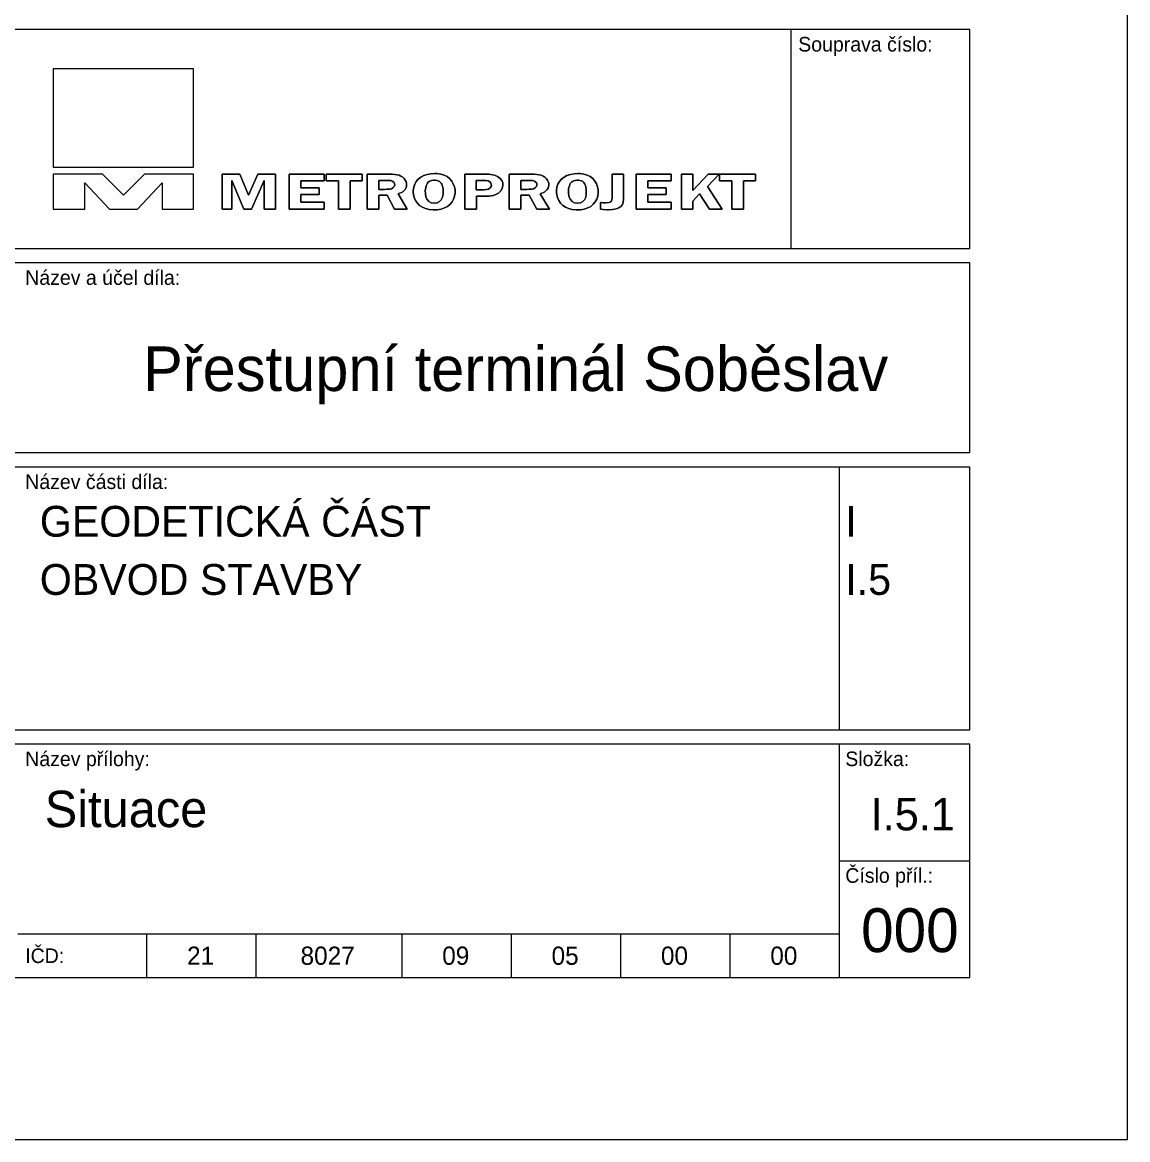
# Model space of a CAD drawing. Extents: x 0.336 to 0.63, y 0 to 0.297.
# Drawn here: x 0.4935 to 0.63, y 0 to 0.1379 of the extents above; entities that cross this region are included whole.
import ezdxf

# ---------------------------------------------------------------- set-up
doc = ezdxf.new("R2010")
doc.units = 0
doc.layers.add('ROZPISKA', color=7, linetype='Continuous')
doc.layers.add('Rozvrzeni', color=7, linetype='Continuous')

msp = doc.modelspace()

# ---------------------------------------------------------------- linework, layer by layer
at = {"layer": 'ROZPISKA'}
for p, q in [((0.51469, 0.13217), (0.49735, 0.13217)), ((0.49735, 0.13217), (0.49735, 0.12003)), ((0.51469, 0.12003), (0.51469, 0.13217)), ((0.49735, 0.12003), (0.51469, 0.12003)), ((0.50342, 0.11916), (0.49735, 0.11916)), ((0.49735, 0.11916), (0.49735, 0.11483)), ((0.50602, 0.11656), (0.50342, 0.11916)), ((0.50862, 0.11916), (0.50602, 0.11656)), ((0.51469, 0.11916), (0.50862, 0.11916)), ((0.51469, 0.11483), (0.51469, 0.11916)), ((0.5182, 0.11483), (0.5182, 0.11918)), ((0.5182, 0.11918), (0.52041, 0.11918)), ((0.52041, 0.11918), (0.52147, 0.11658)), ((0.52147, 0.11658), (0.5226, 0.11918)), ((0.5226, 0.11918), (0.52481, 0.11918)), ((0.52481, 0.11918), (0.52481, 0.11483)), ((0.52647, 0.11483), (0.52647, 0.11918)), ((0.52647, 0.11918), (0.53081, 0.11918)), ((0.53081, 0.11918), (0.53081, 0.11835)), ((0.53107, 0.11832), (0.53107, 0.11918)), ((0.53107, 0.11918), (0.53551, 0.11918)), ((0.53551, 0.11918), (0.53551, 0.11832)), ((0.56932, 0.11483), (0.56932, 0.11918)), ((0.56932, 0.11918), (0.57366, 0.11918)), ((0.57366, 0.11918), (0.57366, 0.11835)), ((0.57492, 0.11483), (0.57492, 0.11918)), ((0.57492, 0.11918), (0.57631, 0.11918)), ((0.57631, 0.11713), (0.57821, 0.11918)), ((0.57631, 0.11918), (0.57631, 0.11713)), ((0.57956, 0.11918), (0.57811, 0.11763)), ((0.57821, 0.11918), (0.57956, 0.11918)), ((0.57963, 0.11832), (0.57963, 0.11918)), ((0.57963, 0.11918), (0.58407, 0.11918)), ((0.58407, 0.11918), (0.58407, 0.11832)), ((0.50125, 0.11483), (0.50125, 0.11808)), ((0.50125, 0.11808), (0.50429, 0.11483)), ((0.50776, 0.11483), (0.51079, 0.11808)), ((0.51079, 0.11808), (0.51079, 0.11483)), ((0.51939, 0.11838), (0.51939, 0.11483)), ((0.52088, 0.11483), (0.51939, 0.11838)), ((0.52338, 0.11838), (0.52185, 0.11483)), ((0.52338, 0.11483), (0.52338, 0.11838)), ((0.52792, 0.11835), (0.52792, 0.11746)), ((0.53081, 0.11835), (0.52792, 0.11835)), ((0.52792, 0.11746), (0.53019, 0.11746)), ((0.53019, 0.11746), (0.53019, 0.11664)), ((0.53258, 0.11832), (0.53107, 0.11832)), ((0.53258, 0.11483), (0.53258, 0.11832)), ((0.53551, 0.11832), (0.53401, 0.11832)), ((0.53401, 0.11832), (0.53401, 0.11483)), ((0.57077, 0.11835), (0.57077, 0.11746)), ((0.57366, 0.11835), (0.57077, 0.11835)), ((0.57077, 0.11746), (0.57304, 0.11746)), ((0.57304, 0.11746), (0.57304, 0.11664)), ((0.57811, 0.11763), (0.57993, 0.11483)), ((0.58113, 0.11832), (0.57963, 0.11832)), ((0.58113, 0.11483), (0.58113, 0.11832)), ((0.58407, 0.11832), (0.58257, 0.11832)), ((0.58257, 0.11832), (0.58257, 0.11483)), ((0.53019, 0.11664), (0.52792, 0.11664)), ((0.52792, 0.11664), (0.52792, 0.11569)), ((0.57304, 0.11664), (0.57077, 0.11664)), ((0.57077, 0.11664), (0.57077, 0.11569)), ((0.57716, 0.11672), (0.57631, 0.11583)), ((0.57836, 0.11483), (0.57716, 0.11672)), ((0.49735, 0.11483), (0.50125, 0.11483)), ((0.50429, 0.11483), (0.50776, 0.11483)), ((0.51079, 0.11483), (0.51469, 0.11483)), ((0.51939, 0.11483), (0.5182, 0.11483)), ((0.52185, 0.11483), (0.52088, 0.11483)), ((0.52481, 0.11483), (0.52338, 0.11483)), ((0.53081, 0.11483), (0.52647, 0.11483)), ((0.52792, 0.11569), (0.53081, 0.11569)), ((0.53081, 0.11569), (0.53081, 0.11483)), ((0.53401, 0.11483), (0.53258, 0.11483)), ((0.57366, 0.11483), (0.56932, 0.11483)), ((0.57077, 0.11569), (0.57366, 0.11569)), ((0.57366, 0.11569), (0.57366, 0.11483)), ((0.57631, 0.11483), (0.57492, 0.11483)), ((0.57631, 0.11583), (0.57631, 0.11483)), ((0.57993, 0.11483), (0.57836, 0.11483)), ((0.58257, 0.11483), (0.58113, 0.11483))]:
    msp.add_line(p, q, dxfattribs=at)
for points in [[(0.4395, 0.11), (0.6105, 0.11), (0.6105, 0.137), (0.4395, 0.137)], [(0.53982, 0.1191), (0.54007, 0.11902), (0.54029, 0.11893), (0.5405, 0.11879), (0.54068, 0.11863), (0.54082, 0.11844), (0.54093, 0.11824), (0.54099, 0.11802), (0.54099, 0.11781), (0.54096, 0.11763), (0.5409, 0.11745), (0.5408, 0.11729), (0.54067, 0.11713), (0.54051, 0.117), (0.54035, 0.1169), (0.54014, 0.11681), (0.54, 0.11677), (0.53995, 0.11675), (0.54107, 0.11483), (0.5395, 0.11483), (0.53857, 0.11655), (0.53755, 0.11655), (0.53755, 0.11483), (0.53612, 0.11483), (0.53612, 0.11918), (0.53879, 0.11918), (0.53919, 0.11917), (0.53953, 0.11914)], [(0.54629, 0.11861), (0.54655, 0.11831), (0.54675, 0.11798), (0.54689, 0.11761), (0.54697, 0.11723), (0.54697, 0.11684), (0.54691, 0.11645), (0.54678, 0.11608), (0.54659, 0.11574), (0.54635, 0.11544), (0.54604, 0.11519), (0.54567, 0.115), (0.54524, 0.11486), (0.54476, 0.11478), (0.54425, 0.11477), (0.54375, 0.11481), (0.54331, 0.11492), (0.54293, 0.11509), (0.54259, 0.11531), (0.54231, 0.1156), (0.54208, 0.11593), (0.54192, 0.11628), (0.54183, 0.11667), (0.54181, 0.11686), (0.54181, 0.11697), (0.54181, 0.11713), (0.54187, 0.11755), (0.54199, 0.11793), (0.54218, 0.11827), (0.54243, 0.11856), (0.54274, 0.11881), (0.54311, 0.119), (0.54352, 0.11914), (0.54398, 0.11922), (0.54445, 0.11925), (0.54471, 0.11924), (0.54519, 0.11917), (0.54561, 0.11905), (0.54598, 0.11886)], [(0.55081, 0.11918), (0.55112, 0.11917), (0.55139, 0.11914), (0.55183, 0.11905), (0.55219, 0.11888), (0.55251, 0.11866), (0.55273, 0.1184), (0.55285, 0.1181), (0.55288, 0.11776), (0.5528, 0.11741), (0.55262, 0.11709), (0.55234, 0.11683), (0.55201, 0.11664), (0.55165, 0.11652), (0.55143, 0.11649), (0.55118, 0.11646), (0.55089, 0.11645), (0.55072, 0.11645), (0.55064, 0.11645), (0.54963, 0.11645), (0.54963, 0.11483), (0.54818, 0.11483), (0.54818, 0.11918), (0.55062, 0.11918)], [(0.55736, 0.1191), (0.55761, 0.11902), (0.55783, 0.11893), (0.55804, 0.11879), (0.55822, 0.11863), (0.55837, 0.11844), (0.55847, 0.11824), (0.55853, 0.11802), (0.55854, 0.11781), (0.55851, 0.11763), (0.55844, 0.11745), (0.55834, 0.11729), (0.55821, 0.11713), (0.55805, 0.117), (0.55789, 0.1169), (0.55768, 0.11681), (0.55755, 0.11677), (0.55749, 0.11675), (0.55861, 0.11483), (0.55704, 0.11483), (0.55611, 0.11655), (0.55509, 0.11655), (0.55509, 0.11483), (0.55366, 0.11483), (0.55366, 0.11918), (0.55633, 0.11918), (0.55673, 0.11917), (0.55707, 0.11914)], [(0.56397, 0.11861), (0.56423, 0.11831), (0.56443, 0.11798), (0.56457, 0.11761), (0.56465, 0.11723), (0.56465, 0.11684), (0.56459, 0.11645), (0.56446, 0.11608), (0.56427, 0.11574), (0.56402, 0.11544), (0.56372, 0.11519), (0.56335, 0.115), (0.56292, 0.11486), (0.56244, 0.11478), (0.56192, 0.11477), (0.56143, 0.11481), (0.56099, 0.11492), (0.5606, 0.11509), (0.56027, 0.11531), (0.55999, 0.1156), (0.55976, 0.11593), (0.5596, 0.11628), (0.55951, 0.11667), (0.55949, 0.11686), (0.55948, 0.11697), (0.55949, 0.11713), (0.55954, 0.11755), (0.55967, 0.11793), (0.55986, 0.11827), (0.56011, 0.11856), (0.56042, 0.11881), (0.56078, 0.119), (0.5612, 0.11914), (0.56166, 0.11922), (0.56212, 0.11925), (0.56238, 0.11924), (0.56286, 0.11917), (0.56329, 0.11905), (0.56365, 0.11886)], [(0.56772, 0.11572), (0.56762, 0.11543), (0.56744, 0.11519), (0.56718, 0.115), (0.56684, 0.11487), (0.56642, 0.11479), (0.56592, 0.11476), (0.56584, 0.11476), (0.56581, 0.11476), (0.56575, 0.11476), (0.56525, 0.11479), (0.5649, 0.11483), (0.5649, 0.11567), (0.565, 0.11566), (0.56524, 0.11563), (0.56559, 0.11562), (0.56601, 0.11568), (0.56616, 0.11575), (0.56626, 0.11584), (0.56633, 0.11602), (0.56634, 0.11616), (0.56634, 0.11622), (0.56634, 0.11918), (0.56776, 0.11918), (0.56776, 0.11608)], [(0.53827, 0.11729), (0.53856, 0.1173), (0.5389, 0.11731), (0.5391, 0.11735), (0.5393, 0.11746), (0.53946, 0.11763), (0.53953, 0.11784), (0.5395, 0.11803), (0.53939, 0.11819), (0.53922, 0.11831), (0.53902, 0.11838), (0.53869, 0.1184), (0.53833, 0.1184), (0.53755, 0.1184), (0.53755, 0.11729)], [(0.54355, 0.11804), (0.54347, 0.11789), (0.5434, 0.11772), (0.54335, 0.11753), (0.54331, 0.11733), (0.54329, 0.11712), (0.5433, 0.11676), (0.54337, 0.11634), (0.54352, 0.11602), (0.54374, 0.11578), (0.54403, 0.11564), (0.5444, 0.11559), (0.54477, 0.11564), (0.54506, 0.11578), (0.54527, 0.11601), (0.54542, 0.11633), (0.54549, 0.11675), (0.5455, 0.11712), (0.54548, 0.11735), (0.54544, 0.11756), (0.54539, 0.11775), (0.54532, 0.11791), (0.54523, 0.11806), (0.54513, 0.11818), (0.54501, 0.11828), (0.54486, 0.11835), (0.5447, 0.11839), (0.54451, 0.11841), (0.5443, 0.11841), (0.54411, 0.11839), (0.54393, 0.11834), (0.54378, 0.11827), (0.54366, 0.11817)], [(0.55085, 0.11726), (0.55111, 0.11733), (0.55129, 0.11746), (0.5514, 0.11759), (0.55145, 0.11774), (0.55144, 0.11791), (0.55138, 0.11807), (0.55125, 0.11821), (0.55105, 0.11832), (0.55079, 0.11838), (0.55049, 0.11839), (0.54957, 0.11839), (0.54957, 0.11724), (0.5505, 0.11724)], [(0.55581, 0.11729), (0.5561, 0.1173), (0.55644, 0.11731), (0.55664, 0.11735), (0.55685, 0.11746), (0.55701, 0.11763), (0.55707, 0.11784), (0.55704, 0.11803), (0.55693, 0.11819), (0.55676, 0.11831), (0.55656, 0.11838), (0.55623, 0.1184), (0.55587, 0.1184), (0.55509, 0.1184), (0.55509, 0.11729)], [(0.56123, 0.11804), (0.56115, 0.11789), (0.56108, 0.11772), (0.56102, 0.11753), (0.56099, 0.11733), (0.56097, 0.11712), (0.56098, 0.11676), (0.56105, 0.11634), (0.5612, 0.11602), (0.56142, 0.11578), (0.56171, 0.11564), (0.56207, 0.11559), (0.56244, 0.11564), (0.56274, 0.11578), (0.56295, 0.11601), (0.5631, 0.11633), (0.56317, 0.11675), (0.56317, 0.11712), (0.56316, 0.11735), (0.56312, 0.11756), (0.56307, 0.11775), (0.563, 0.11791), (0.56291, 0.11806), (0.56281, 0.11818), (0.56269, 0.11828), (0.56254, 0.11835), (0.56238, 0.11839), (0.56219, 0.11841), (0.56198, 0.11841), (0.56178, 0.11839), (0.56161, 0.11834), (0.56146, 0.11827), (0.56133, 0.11817)], [(0.4395, 0.0848), (0.6105, 0.0848), (0.6105, 0.1082), (0.4395, 0.1082)], [(0.4395, 0.0506), (0.6105, 0.0506), (0.6105, 0.083), (0.4395, 0.083)], [(0.4395, 0.02), (0.6105, 0.02), (0.6105, 0.0488), (0.4395, 0.0488)]]:
    msp.add_lwpolyline(points, close=True, dxfattribs=at)
for points in [[(0.58843, 0.137), (0.58843, 0.11)], [(0.51469, 0.13217), (0.49735, 0.13217), (0.49735, 0.12003), (0.51469, 0.12003), (0.51469, 0.13217)], [(0.50125, 0.11808), (0.50429, 0.11483), (0.50776, 0.11483), (0.51079, 0.11808), (0.51079, 0.11483), (0.51469, 0.11483), (0.51469, 0.11916), (0.50862, 0.11916), (0.50602, 0.11656), (0.50342, 0.11916), (0.49735, 0.11916), (0.49735, 0.11483), (0.50125, 0.11483), (0.50125, 0.11808)], [(0.52041, 0.11918), (0.5182, 0.11918), (0.5182, 0.11483), (0.51939, 0.11483), (0.51939, 0.11838), (0.52088, 0.11483), (0.52185, 0.11483), (0.52338, 0.11838), (0.52338, 0.11483), (0.52481, 0.11483), (0.52481, 0.11918), (0.5226, 0.11918), (0.52147, 0.11658), (0.52041, 0.11918)], [(0.53081, 0.11918), (0.52647, 0.11918), (0.52647, 0.11483), (0.53081, 0.11483), (0.53081, 0.11569), (0.52792, 0.11569), (0.52792, 0.11664), (0.53019, 0.11664), (0.53019, 0.11746), (0.52792, 0.11746), (0.52792, 0.11835), (0.53081, 0.11835), (0.53081, 0.11918)], [(0.53551, 0.11918), (0.53107, 0.11918), (0.53107, 0.11832), (0.53258, 0.11832), (0.53258, 0.11483), (0.53401, 0.11483), (0.53401, 0.11832), (0.53551, 0.11832), (0.53551, 0.11918)], [(0.54093, 0.11824), (0.54082, 0.11844), (0.54068, 0.11863), (0.5405, 0.11879), (0.54029, 0.11893), (0.54007, 0.11902), (0.53982, 0.1191), (0.53953, 0.11914), (0.53919, 0.11917), (0.53879, 0.11918), (0.53612, 0.11918), (0.53612, 0.11483), (0.53755, 0.11483), (0.53755, 0.11655), (0.53857, 0.11655), (0.5395, 0.11483), (0.54107, 0.11483), (0.53995, 0.11675), (0.54, 0.11677), (0.54014, 0.11681), (0.54035, 0.1169), (0.54051, 0.117), (0.54067, 0.11713), (0.5408, 0.11729), (0.5409, 0.11745), (0.54096, 0.11763), (0.54099, 0.11781), (0.54099, 0.11802), (0.54093, 0.11824)], [(0.54675, 0.11798), (0.54655, 0.11831), (0.54629, 0.11861), (0.54598, 0.11886), (0.54561, 0.11905), (0.54519, 0.11917), (0.54471, 0.11924), (0.54445, 0.11925), (0.54398, 0.11922), (0.54352, 0.11914), (0.54311, 0.119), (0.54274, 0.11881), (0.54243, 0.11856), (0.54218, 0.11827), (0.54199, 0.11793), (0.54187, 0.11755), (0.54181, 0.11713), (0.54181, 0.11697), (0.54181, 0.11686), (0.54183, 0.11667), (0.54192, 0.11628), (0.54208, 0.11593), (0.54231, 0.1156), (0.54259, 0.11531), (0.54293, 0.11509), (0.54331, 0.11492), (0.54375, 0.11481), (0.54425, 0.11477), (0.54476, 0.11478), (0.54524, 0.11486), (0.54567, 0.115), (0.54604, 0.11519), (0.54635, 0.11544), (0.54659, 0.11574), (0.54678, 0.11608), (0.54691, 0.11645), (0.54697, 0.11684), (0.54697, 0.11723), (0.54689, 0.11761), (0.54675, 0.11798)], [(0.5528, 0.11741), (0.55288, 0.11776), (0.55285, 0.1181), (0.55273, 0.1184), (0.55251, 0.11866), (0.55219, 0.11888), (0.55183, 0.11905), (0.55139, 0.11914), (0.55112, 0.11917), (0.55081, 0.11918), (0.55062, 0.11918), (0.54818, 0.11918), (0.54818, 0.11483), (0.54963, 0.11483), (0.54963, 0.11645), (0.55064, 0.11645), (0.55072, 0.11645), (0.55089, 0.11645), (0.55118, 0.11646), (0.55143, 0.11649), (0.55165, 0.11652), (0.55201, 0.11664), (0.55234, 0.11683), (0.55262, 0.11709), (0.5528, 0.11741)], [(0.55844, 0.11745), (0.55851, 0.11763), (0.55854, 0.11781), (0.55853, 0.11802), (0.55847, 0.11824), (0.55837, 0.11844), (0.55822, 0.11863), (0.55804, 0.11879), (0.55783, 0.11893), (0.55761, 0.11902), (0.55736, 0.1191), (0.55707, 0.11914), (0.55673, 0.11917), (0.55633, 0.11918), (0.55366, 0.11918), (0.55366, 0.11483), (0.55509, 0.11483), (0.55509, 0.11655), (0.55611, 0.11655), (0.55704, 0.11483), (0.55861, 0.11483), (0.55749, 0.11675), (0.55755, 0.11677), (0.55768, 0.11681), (0.55789, 0.1169), (0.55805, 0.117), (0.55821, 0.11713), (0.55834, 0.11729), (0.55844, 0.11745)], [(0.56465, 0.11723), (0.56457, 0.11761), (0.56443, 0.11798), (0.56423, 0.11831), (0.56397, 0.11861), (0.56365, 0.11886), (0.56329, 0.11905), (0.56286, 0.11917), (0.56238, 0.11924), (0.56212, 0.11925), (0.56166, 0.11922), (0.5612, 0.11914), (0.56078, 0.119), (0.56042, 0.11881), (0.56011, 0.11856), (0.55986, 0.11827), (0.55967, 0.11793), (0.55954, 0.11755), (0.55949, 0.11713), (0.55948, 0.11697), (0.55949, 0.11686), (0.55951, 0.11667), (0.5596, 0.11628), (0.55976, 0.11593), (0.55999, 0.1156), (0.56027, 0.11531), (0.5606, 0.11509), (0.56099, 0.11492), (0.56143, 0.11481), (0.56192, 0.11477), (0.56244, 0.11478), (0.56292, 0.11486), (0.56335, 0.115), (0.56372, 0.11519), (0.56402, 0.11544), (0.56427, 0.11574), (0.56446, 0.11608), (0.56459, 0.11645), (0.56465, 0.11684), (0.56465, 0.11723)], [(0.56776, 0.11918), (0.56634, 0.11918), (0.56634, 0.11616), (0.56633, 0.11602), (0.56626, 0.11584), (0.56616, 0.11575), (0.56601, 0.11568), (0.56559, 0.11562), (0.56524, 0.11563), (0.565, 0.11566), (0.5649, 0.11567), (0.5649, 0.11483), (0.56525, 0.11479), (0.56575, 0.11476), (0.56581, 0.11476), (0.56584, 0.11476), (0.56592, 0.11476), (0.56642, 0.11479), (0.56684, 0.11487), (0.56718, 0.115), (0.56744, 0.11519), (0.56762, 0.11543), (0.56772, 0.11572), (0.56776, 0.11608), (0.56776, 0.11918)], [(0.57304, 0.11746), (0.57077, 0.11746), (0.57077, 0.11835), (0.57366, 0.11835), (0.57366, 0.11918), (0.56932, 0.11918), (0.56932, 0.11483), (0.57366, 0.11483), (0.57366, 0.11569), (0.57077, 0.11569), (0.57077, 0.11664), (0.57304, 0.11664), (0.57304, 0.11746)], [(0.57631, 0.11918), (0.57492, 0.11918), (0.57492, 0.11483), (0.57631, 0.11483), (0.57631, 0.11583), (0.57716, 0.11672), (0.57836, 0.11483), (0.57993, 0.11483), (0.57811, 0.11763), (0.57956, 0.11918), (0.57821, 0.11918), (0.57631, 0.11713), (0.57631, 0.11918)], [(0.58257, 0.11832), (0.58407, 0.11832), (0.58407, 0.11918), (0.57963, 0.11918), (0.57963, 0.11832), (0.58113, 0.11832), (0.58113, 0.11483), (0.58257, 0.11483), (0.58257, 0.11832)], [(0.53755, 0.1184), (0.53833, 0.1184), (0.53869, 0.1184), (0.53902, 0.11838), (0.53922, 0.11831), (0.53939, 0.11819), (0.5395, 0.11803), (0.53953, 0.11784), (0.53946, 0.11763), (0.5393, 0.11746), (0.5391, 0.11735), (0.5389, 0.11731), (0.53856, 0.1173), (0.53827, 0.11729), (0.53755, 0.11729), (0.53755, 0.1184)], [(0.5434, 0.11772), (0.54347, 0.11789), (0.54355, 0.11804), (0.54366, 0.11817), (0.54378, 0.11827), (0.54393, 0.11834), (0.54411, 0.11839), (0.5443, 0.11841), (0.54451, 0.11841), (0.5447, 0.11839), (0.54486, 0.11835), (0.54501, 0.11828), (0.54513, 0.11818), (0.54523, 0.11806), (0.54532, 0.11791), (0.54539, 0.11775), (0.54544, 0.11756), (0.54548, 0.11735), (0.5455, 0.11712), (0.54549, 0.11675), (0.54542, 0.11633), (0.54527, 0.11601), (0.54506, 0.11578), (0.54477, 0.11564), (0.5444, 0.11559), (0.54403, 0.11564), (0.54374, 0.11578), (0.54352, 0.11602), (0.54337, 0.11634), (0.5433, 0.11676), (0.54329, 0.11712), (0.54331, 0.11733), (0.54335, 0.11753), (0.5434, 0.11772)], [(0.54957, 0.11839), (0.55049, 0.11839), (0.55079, 0.11838), (0.55105, 0.11832), (0.55125, 0.11821), (0.55138, 0.11807), (0.55144, 0.11791), (0.55145, 0.11774), (0.5514, 0.11759), (0.55129, 0.11746), (0.55111, 0.11733), (0.55085, 0.11726), (0.5505, 0.11724), (0.54957, 0.11724), (0.54957, 0.11839)], [(0.55509, 0.1184), (0.55587, 0.1184), (0.55623, 0.1184), (0.55656, 0.11838), (0.55676, 0.11831), (0.55693, 0.11819), (0.55704, 0.11803), (0.55707, 0.11784), (0.55701, 0.11763), (0.55685, 0.11746), (0.55664, 0.11735), (0.55644, 0.11731), (0.5561, 0.1173), (0.55581, 0.11729), (0.55509, 0.11729), (0.55509, 0.1184)], [(0.56097, 0.11712), (0.56099, 0.11733), (0.56102, 0.11753), (0.56108, 0.11772), (0.56115, 0.11789), (0.56123, 0.11804), (0.56133, 0.11817), (0.56146, 0.11827), (0.56161, 0.11834), (0.56178, 0.11839), (0.56198, 0.11841), (0.56219, 0.11841), (0.56238, 0.11839), (0.56254, 0.11835), (0.56269, 0.11828), (0.56281, 0.11818), (0.56291, 0.11806), (0.563, 0.11791), (0.56307, 0.11775), (0.56312, 0.11756), (0.56316, 0.11735), (0.56317, 0.11712), (0.56317, 0.11675), (0.5631, 0.11633), (0.56295, 0.11601), (0.56274, 0.11578), (0.56244, 0.11564), (0.56207, 0.11559), (0.56171, 0.11564), (0.56142, 0.11578), (0.5612, 0.11602), (0.56105, 0.11634), (0.56098, 0.11676), (0.56097, 0.11712)], [(0.4395, 0.11), (0.6105, 0.11)], [(0.59438, 0.083), (0.59438, 0.0506)], [(0.59438, 0.0488), (0.59438, 0.02)], [(0.59438, 0.0344), (0.6105, 0.0344)], [(0.493, 0.0254), (0.59438, 0.0254)], [(0.50888, 0.0254), (0.50888, 0.02)], [(0.52238, 0.0254), (0.52238, 0.02)], [(0.54038, 0.0254), (0.54038, 0.02)], [(0.55388, 0.0254), (0.55388, 0.02)], [(0.56738, 0.0254), (0.56738, 0.02)], [(0.58088, 0.0254), (0.58088, 0.02)]]:
    msp.add_lwpolyline(points, dxfattribs=at)
at = {"layer": 'Rozvrzeni'}
msp.add_lwpolyline([(0.42, 0), (0.63, 0), (0.63, 0.297), (0.42, 0.297)], close=True, dxfattribs=at)

# ---------------------------------------------------------------- texts
at = {"layer": 'ROZPISKA'}
for s, height, p in [('Souprava číslo:', 0.0018, (0.58933, 0.1343)), ('Název a účel díla:', 0.0018, (0.4939, 0.1055)), ('Přestupní terminál Soběslav', 0.0055, (0.50845, 0.0924)), ('Název části díla:', 0.0018, (0.4939, 0.0803)), ('GEODETICKÁ ČÁST', 0.0038, (0.4957, 0.07442)), ('I', 0.0038, (0.59514, 0.07442)), ('OBVOD STAVBY', 0.0038, (0.4957, 0.06724)), ('I.5', 0.0038, (0.59514, 0.06724)), ('Název přílohy:', 0.0018, (0.4939, 0.0461)), ('Složka:', 0.0018, (0.59514, 0.0461)), ('Situace', 0.0045, (0.49631, 0.03857)), ('I.5.1', 0.004, (0.59827, 0.03817)), ('Číslo příl.:', 0.0018, (0.59514, 0.0317)), ('000', 0.0054, (0.59709, 0.02315)), ('IČD:', 0.0018, (0.4939, 0.0218)), ('21', 0.00225, (0.51388, 0.02158)), ('8027', 0.00225, (0.52789, 0.02158)), ('09', 0.00225, (0.54538, 0.02158)), ('05', 0.00225, (0.55888, 0.02158)), ('00', 0.00225, (0.57238, 0.02158)), ('00', 0.00225, (0.58588, 0.02158))]:
    msp.add_text(s, height=height, dxfattribs=at).set_placement(p)

doc.saveas('drawing.dxf')
